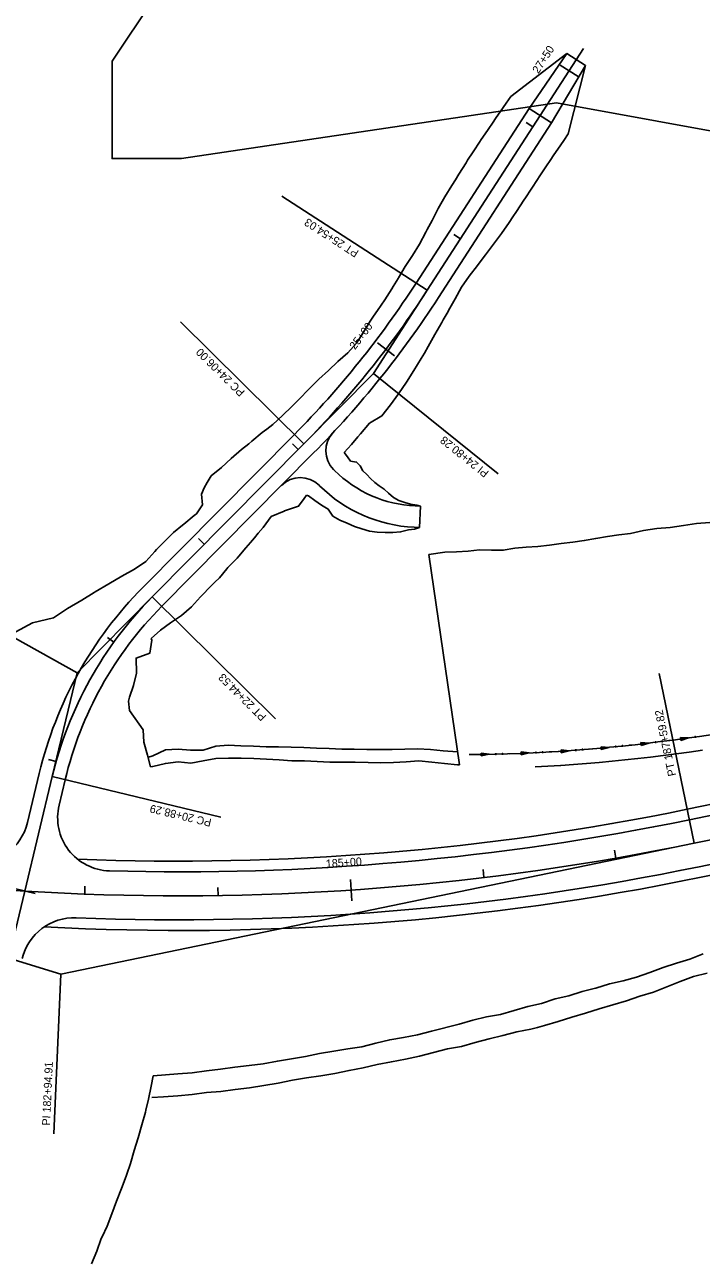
# Model space of a CAD drawing. Extents: x 979959 to 994833, y 1835619 to 1845316.
# Drawn here: x 984070 to 984578, y 1837450 to 1838378 of the extents above; entities that cross this region are included whole.
import ezdxf

# ---------------------------------------------------------------- set-up
doc = ezdxf.new("R2010")
doc.units = 0
for name, color, linetype in [('43', 7, 'Continuous'), ('Future 5 Lane Construction Limits', 7, 'Continuous'), ('R_Horz Alg', 7, 'Continuous'), ('R_Horz Alg Annot', 7, 'Continuous'), ('R_Horz Alg Annot_Side Road', 7, 'Continuous'), ('R_Horz Alg Stationing', 7, 'Continuous'), ('R_Horz Alg Stationing_Side Road', 7, 'Continuous'), ('R_Proposed Const Limits', 7, 'Continuous'), ('R_Proposed Road', 7, 'Continuous'), ('R_Special Ditch', 7, 'Continuous')]:
    doc.layers.add(name, color=color, linetype=linetype)

msp = doc.modelspace()

# ---------------------------------------------------------------- linework, layer by layer
at = {"layer": '43'}
msp.add_lwpolyline([(985729.8, 1837558.64), (985521.45, 1837673.22), (985396.47, 1837819.08), (985333.96, 1837902.41), (985188.08, 1838006.57), (985073.51, 1838162.87), (984990.18, 1838225.38), (984698.45, 1838277.45), (984469.3, 1838319.11), (984188, 1838277.43), (984135.93, 1838277.43), (984135.89, 1838350.34), (984198.39, 1838444.12), (984198.44, 1838496.23), (984083.82, 1838590), (983937.96, 1838704.54)], dxfattribs=at)
at = {"layer": 'Future 5 Lane Construction Limits'}
for points in [[(984162.55, 1837828.4), (984166.49, 1837829.56), (984175.97, 1837834.1), (984185.4, 1837834.68), (984194.82, 1837833.95), (984204.25, 1837833.77), (984213.64, 1837836.74), (984223.04, 1837837.47), (984232.46, 1837837.15), (984241.89, 1837836.8), (984251.33, 1837836.29), (984260.76, 1837836.31), (984270.21, 1837836), (984279.66, 1837835.71), (984289.13, 1837835.31), (984298.61, 1837834.96), (984308.09, 1837834.65), (984317.57, 1837834.49), (984327.05, 1837834.44), (984336.54, 1837834.43), (984346.04, 1837834.41), (984355.52, 1837834.59), (984365.02, 1837834.8), (984374.58, 1837834.36), (984384.24, 1837833.21), (984394.98, 1837832.55)], [(984165.82, 1837573.32), (984174.47, 1837573.85), (984185.26, 1837574.74), (984196.04, 1837575.66), (984206.81, 1837577.02), (984217.57, 1837577.79), (984228.31, 1837579.37), (984239.04, 1837580.66), (984249.75, 1837582.38), (984260.44, 1837584.13), (984271.11, 1837586.27), (984281.77, 1837588.14), (984292.43, 1837589.65), (984303.06, 1837591.47), (984313.66, 1837593.73), (984324.26, 1837595.65), (984334.81, 1837598.04), (984345.37, 1837600.16), (984355.93, 1837602.1), (984366.44, 1837604.43), (984376.91, 1837607.11), (984387.35, 1837609.85), (984397.87, 1837611.68), (984408.27, 1837614.54), (984418.66, 1837617.27), (984429.05, 1837619.94), (984439.42, 1837622.66), (984449.87, 1837624.59), (984454.86, 1837625.85), (984460.2, 1837627.42), (984470.49, 1837630.4), (984480.7, 1837633.75), (984490.98, 1837636.62), (984501.2, 1837639.75), (984511.38, 1837642.99), (984521.6, 1837645.95), (984531.72, 1837649.39), (984541.9, 1837652.37), (984551.86, 1837656.47), (984561.84, 1837660.37), (984571.82, 1837664.17), (984582.07, 1837666.51)]]:
    msp.add_lwpolyline(points, dxfattribs=at)
at = {"layer": 'R_Horz Alg'}
for p, q in [((984572.47, 1837764.03), (990033.82, 1838891.48)), ((984372.29, 1838178.66), (984489.55, 1838360.02)), ((984372.29, 1838178.66), (984489.55, 1838360.02)), ((984372.29, 1838178.66), (984489.55, 1838360.02)), ((984166.05, 1837948.8), (984279.68, 1838063.51)), ((984166.05, 1837948.8), (984279.68, 1838063.51)), ((984166.05, 1837948.8), (984279.68, 1838063.51)), ((984070.41, 1837728.11), (984090.99, 1837813.97)), ((984070.41, 1837728.11), (984090.99, 1837813.97)), ((984070.41, 1837728.11), (984090.99, 1837813.97)), ((984003.15, 1837447.52), (984070.41, 1837728.11))]:
    msp.add_line(p, q, dxfattribs=at)
for centre, radius, start, end in [((983770.86, 1838567.53), 716.2, 315.27137, 327.11389), ((983770.86, 1838567.53), 716.2, 315.27137, 327.11389), ((983770.86, 1838567.53), 716.2, 315.27137, 327.11389), ((984369.58, 1837747.19), 286.48, 135.27137, 166.51989), ((984369.58, 1837747.19), 286.48, 135.27137, 166.51989), ((984369.58, 1837747.19), 286.48, 135.27137, 166.51989), ((984186.34, 1839634.45), 1909.86, 253.16792, 281.66438)]:
    msp.add_arc(centre, radius, start, end, dxfattribs=at)
at = {"layer": 'R_Horz Alg Annot'}
for points in [[(984572.47, 1837764.03), (984546.19, 1837891.35)], [(984097.51, 1837665.98), (984092.1, 1837546.1)]]:
    msp.add_lwpolyline(points, dxfattribs=at)
at = {"layer": 'R_Horz Alg Annot_Side Road'}
for p, q in [((984331.96, 1838116.28), (984372.29, 1838178.66)), ((984331.96, 1838116.28), (984279.68, 1838063.51)), ((984109.67, 1837891.88), (984166.05, 1837948.8)), ((984090.99, 1837813.97), (984109.67, 1837891.88)), ((983633.31, 1837806.41), (984097.51, 1837665.98)), ((984572.47, 1837764.03), (984097.51, 1837665.98))]:
    msp.add_line(p, q, dxfattribs=at)
for points in [[(984372.29, 1838178.66), (984263.12, 1838249.25)], [(984279.68, 1838063.51), (984187.32, 1838155)], [(984331.96, 1838116.28), (984425.47, 1838041.08)], [(984109.67, 1837891.88), (984004.82, 1837950.25)], [(984166.05, 1837948.8), (984258.41, 1837857.31)], [(984090.99, 1837813.97), (984217.41, 1837783.66)]]:
    msp.add_lwpolyline(points, dxfattribs=at)
at = {"layer": 'R_Horz Alg Stationing'}
for points in [[(984512.69, 1837758.77), (984513.71, 1837752.86)], [(984314.7, 1837736.93), (984315.78, 1837720.96)], [(984414.07, 1837744.26), (984414.79, 1837738.3)], [(984115.58, 1837731.91), (984115.35, 1837725.91)], [(984215.25, 1837730.81), (984215.34, 1837724.81)]]:
    msp.add_lwpolyline(points, dxfattribs=at)
at = {"layer": 'R_Horz Alg Stationing_Side Road'}
for points in [[(984471.98, 1838347.57), (984485.41, 1838338.88)], [(984446.51, 1838304.5), (984451.55, 1838301.24)], [(984392.21, 1838220.52), (984397.25, 1838217.26)], [(984334.9, 1838139.28), (984347.64, 1838129.6)], [(984271.2, 1838063.47), (984275.46, 1838059.25)], [(984200.82, 1837992.43), (984205.08, 1837988.2)], [(984132.42, 1837918.37), (984137.29, 1837914.86)], [(984088.18, 1837826.93), (984093.95, 1837825.3)], [(984062.63, 1837729.98), (984078.19, 1837726.25)]]:
    msp.add_lwpolyline(points, dxfattribs=at)
at = {"layer": 'R_Proposed Const Limits'}
for p, q in [((984434.96, 1838323.87), (984476.93, 1838356.27)), ((984478.05, 1838296.01), (984490.99, 1838347.18)), ((984396.12, 1837628.41), (984375.41, 1837623.02))]:
    msp.add_line(p, q, dxfattribs=at)
for points in [[(984319.16, 1838139.02), (984324.33, 1838147.3), (984329.47, 1838155.56), (984332.04, 1838159.27), (984334.96, 1838163.55), (984340.37, 1838171.59), (984345.58, 1838179.76), (984346.69, 1838181.54), (984350.33, 1838187.39), (984350.69, 1838187.98), (984355.77, 1838196.45), (984361.2, 1838204.85), (984366.55, 1838213.29), (984371.19, 1838222.21), (984372.17, 1838224.16), (984375.97, 1838231.02), (984380.35, 1838240.1), (984385.45, 1838248.71), (984390.74, 1838257.2), (984393.43, 1838261.49), (984395.98, 1838265.72), (984401.32, 1838274.17), (984402.56, 1838276.12), (984406.71, 1838282.59), (984412.05, 1838290.51), (984412.31, 1838290.89), (984417.94, 1838299.15), (984421.75, 1838304.77), (984423.55, 1838307.43), (984429.15, 1838315.72), (984431.4, 1838319.06), (984434.96, 1838323.87)], [(984398.03, 1838181.04), (984403.68, 1838189.29), (984409.94, 1838197.15), (984411.25, 1838198.88), (984415.97, 1838205.16), (984421.94, 1838213.21), (984427.83, 1838221.31), (984433.6, 1838229.49), (984436.45, 1838233.67), (984439.23, 1838237.75), (984444.71, 1838246.12), (984445.99, 1838248.04), (984450.24, 1838254.45), (984455.41, 1838262.48), (984455.63, 1838262.87), (984461.14, 1838271.22), (984464.95, 1838276.84), (984466.8, 1838279.47), (984472.47, 1838287.71), (984474.72, 1838291.05), (984478.05, 1838296.01)], [(984309.89, 1838057.01), (984315.41, 1838063.13), (984320.28, 1838068.69), (984322.21, 1838070.95), (984328.85, 1838078.9), (984338.3, 1838084.46), (984344.63, 1838092.72), (984350.78, 1838101.13), (984350.79, 1838101.14), (984356.63, 1838109.74), (984362.23, 1838118.53), (984367.67, 1838127.39), (984370.11, 1838131.57), (984372.89, 1838136.39), (984378.04, 1838145.4), (984383.08, 1838154.45), (984384.17, 1838156.42), (984387.85, 1838162.77), (984388.21, 1838163.42), (984393.15, 1838172.28), (984398.03, 1838181.04)], [(984199.09, 1838011), (984203.7, 1838017.73), (984202.99, 1838025.85), (984204.98, 1838030.54), (984207.12, 1838034.56), (984210.13, 1838039.51), (984217.9, 1838045.89), (984225.15, 1838052.43), (984225.3, 1838052.63), (984232.89, 1838059.19), (984238.51, 1838063.47), (984240.7, 1838065.53), (984248.46, 1838071.92), (984251.94, 1838074.44), (984256.4, 1838078.13), (984263.65, 1838084.82), (984270.64, 1838091.46), (984277.52, 1838098.22), (984282.32, 1838103.15), (984284.23, 1838105.15), (984290.95, 1838112.09), (984298.16, 1838118.63), (984305.3, 1838125.28), (984312.71, 1838131.74), (984312.73, 1838131.75), (984319.16, 1838139.02)], [(984309.89, 1838057.01), (984312.38, 1838053.89), (984314.76, 1838050.57), (984319.2, 1838049.79), (984321.97, 1838047.12), (984323.96, 1838043.18), (984326.98, 1838040.55), (984329.81, 1838037.42), (984332.94, 1838034.58), (984336.29, 1838031.94), (984339.82, 1838029.49), (984343.3, 1838026.42), (984346.98, 1838023.35), (984351.02, 1838021.09), (984355.33, 1838019.64), (984359.73, 1838018.33), (984364.35, 1838017.46), (984367.11, 1838016.75)], [(984255.18, 1838008.96), (984264.95, 1838013.01), (984265.11, 1838013.2), (984275.75, 1838016.74), (984279.85, 1838022.52), (984281.75, 1838025.11)], [(984281.75, 1838025.11), (984283.29, 1838024.52), (984288.05, 1838021.05), (984292.9, 1838017.63), (984298, 1838014.63), (984301.5, 1838009.32), (984306.65, 1838006.3), (984312.16, 1838003.97), (984317.62, 1838001.66), (984323.19, 1837999.69), (984328.85, 1837998.02), (984334.76, 1837997.34), (984340.66, 1837997.04), (984346.53, 1837997.16), (984352.3, 1837997.43), (984358.08, 1837998.99), (984362.78, 1837999.55), (984366.35, 1838000.77)], [(984063.84, 1837922.44), (984076.19, 1837929.25), (984092, 1837933.17), (984102.5, 1837939.97), (984113.15, 1837946.26), (984122.54, 1837952.07), (984123.27, 1837952.56), (984133.43, 1837958.49), (984143.23, 1837964.42), (984152.79, 1837969.63), (984161.23, 1837975.34), (984168.04, 1837982.68), (984169.29, 1837984.36), (984174.88, 1837989.97), (984178.67, 1837993.79), (984182.06, 1837996.93), (984188.78, 1838002.5), (984189.83, 1838003.32), (984197.58, 1838009.71), (984199.09, 1838011)], [(984165.26, 1837917.55), (984172.3, 1837923.71), (984179.77, 1837929.35), (984187.91, 1837934.84), (984195.49, 1837941.41), (984202.32, 1837948.71), (984203.74, 1837950.24), (984209.1, 1837956.07), (984213.01, 1837959.77), (984216.35, 1837962.97), (984221.89, 1837969.7), (984222.73, 1837970.72), (984229.75, 1837977.85), (984231.04, 1837979.35), (984236.29, 1837985.44), (984239.74, 1837989.44), (984242.82, 1837993.05), (984245.54, 1837996.5), (984249.12, 1838000.89), (984255.18, 1838008.96)], [(984385.39, 1837982.33), (984394.14, 1837982.58), (984402.88, 1837982.96), (984411.53, 1837984.07), (984420.37, 1837983.87), (984429.21, 1837983.74), (984437.83, 1837985.2), (984446.39, 1837985.99), (984446.54, 1837986), (984455.29, 1837986.65), (984464.02, 1837987.44), (984472.68, 1837988.69), (984481.37, 1837989.8), (984490.04, 1837990.99), (984498.66, 1837992.55), (984507.3, 1837993.96), (984515.98, 1837995.2), (984524.71, 1837996.32), (984534.45, 1837998.6), (984544.38, 1837999.94), (984554.39, 1838000.9), (984564.34, 1838002.2), (984574.24, 1838003.67), (984584.29, 1838004.48)], [(984385.39, 1837982.33), (984373.52, 1837980.5), (984396.4, 1837822.75)], [(984164.71, 1837821.21), (984162.34, 1837830.17), (984159.78, 1837839.82), (984159.2, 1837848.99), (984148.95, 1837863.62), (984148.1, 1837870.48), (984149.02, 1837873.62), (984151.99, 1837882.22), (984154.1, 1837891.56), (984153.91, 1837902.86), (984164.24, 1837906.59), (984165.74, 1837916.25), (984165.26, 1837917.55)], [(984164.71, 1837821.21), (984166.41, 1837821.68), (984175.91, 1837823.92), (984185.39, 1837824.99), (984194.87, 1837824.11), (984204.33, 1837825.9), (984213.78, 1837827.59), (984223.24, 1837827.85), (984232.7, 1837827.92), (984242.18, 1837827.48), (984251.66, 1837827.06), (984261.16, 1837826.58), (984270.68, 1837825.95), (984280.18, 1837825.79), (984289.7, 1837825.33), (984299.23, 1837824.94), (984308.75, 1837824.84), (984318.28, 1837824.8), (984327.82, 1837824.59), (984337.38, 1837824.38), (984346.91, 1837824.59), (984356.42, 1837825.01), (984365.9, 1837825.89), (984375.59, 1837824.71), (984385.28, 1837823.78), (984395, 1837822.73), (984396.4, 1837822.75)], [(984396.12, 1837628.41), (984406.43, 1837631.27), (984416.75, 1837633.93), (984427.16, 1837635.64), (984437.42, 1837638.52), (984447.65, 1837641.54), (984457.95, 1837643.87), (984468.09, 1837647.28), (984478.38, 1837649.58), (984488.51, 1837652.78), (984498.53, 1837655.43), (984498.71, 1837655.49), (984508.84, 1837658.55), (984519.06, 1837660.98), (984529.25, 1837663.57), (984539.27, 1837667.02), (984549.22, 1837670.77), (984559.24, 1837674.07), (984569.27, 1837677.22), (984579.15, 1837681.07)], [(984166.82, 1837589.62), (984185.27, 1837591.08), (984195.96, 1837592), (984206.64, 1837593.3), (984217.31, 1837594.62), (984227.97, 1837596.08), (984238.62, 1837597.27), (984249.25, 1837598.68), (984259.85, 1837600.64), (984270.45, 1837602.27), (984281.01, 1837604.25), (984291.56, 1837606.29), (984302.11, 1837608.13), (984312.65, 1837609.81), (984323.19, 1837611.46), (984333.64, 1837614.14), (984344.07, 1837616.71), (984354.56, 1837618.43), (984365.03, 1837620.39), (984375.41, 1837623.02)], [(984120.47, 1837448.75), (984124.41, 1837458.08), (984127.82, 1837467.55), (984128.43, 1837468.91), (984132.19, 1837476.79), (984135.83, 1837486.2), (984139.2, 1837495.67), (984142.96, 1837505.05), (984146.5, 1837514.49), (984146.97, 1837515.88), (984149.67, 1837524.01), (984152.57, 1837533.6), (984155.44, 1837543.2), (984158.24, 1837552.81), (984160.86, 1837562.46), (984161.23, 1837563.88), (984163.29, 1837572.17), (984165.26, 1837581.98), (984166.82, 1837589.62)]]:
    msp.add_lwpolyline(points, dxfattribs=at)
at = {"layer": 'R_Proposed Road'}
for p, q in [((984567.22, 1837789.49), (990028.56, 1838916.94)), ((984568.84, 1837781.66), (990030.18, 1838909.11)), ((984576.11, 1837746.4), (990037.46, 1838873.85)), ((984577.73, 1837738.57), (990039.08, 1838866.02)), ((984448.58, 1838315.07), (984476.93, 1838356.27)), ((984476.93, 1838356.27), (984490.99, 1838347.18)), ((984465.37, 1838304.21), (984490.99, 1838347.18)), ((984363.89, 1838184.09), (984448.58, 1838315.07)), ((984448.58, 1838315.07), (984465.37, 1838304.21)), ((984380.69, 1838173.23), (984465.37, 1838304.21)), ((984158.94, 1837955.84), (984272.58, 1838070.55)), ((984173.15, 1837941.76), (984286.79, 1838056.47)), ((984302.01, 1838044.21), (984302.75, 1838043.48)), ((984291.14, 1838032.45), (984291.49, 1838032.11)), ((984363.11, 1838016.94), (984367.11, 1838016.75)), ((984367.11, 1838016.75), (984366.35, 1838000.77)), ((984366.35, 1838000.77), (984362.35, 1838000.96)), ((984081.27, 1837816.3), (984072.46, 1837779.58)), ((984100.72, 1837811.64), (984096.16, 1837792.62))]:
    msp.add_line(p, q, dxfattribs=at)
for centre, radius, start, end in [((983770.86, 1838567.53), 706.2, 315.27137, 327.11389), ((983770.86, 1838567.53), 726.2, 315.27137, 327.11389), ((984316.25, 1838058.26), 20, 136.96135, 224.62497), ((984367.49, 1838108.84), 92, 225.27137, 267.27137), ((984277.07, 1838018.24), 20, 45.27137, 135.27137), ((984367.49, 1838108.84), 108, 225.27137, 267.27137), ((984277.41, 1838017.9), 20, 45.27126, 45.27137), ((984369.58, 1837747.19), 296.48, 135.27137, 166.51989), ((984369.58, 1837747.19), 276.48, 135.27137, 166.51989), ((984135.06, 1837783.3), 40, 166.51989, 268.41302), ((984186.34, 1839634.45), 1883.86, 267.67679, 281.66438), ((984033.57, 1837788.9), 40, 265.26778, 346.51989), ((984186.34, 1839634.45), 1891.86, 268.41302, 281.66438), ((984186.34, 1839634.45), 1927.86, 267.70261, 281.66438), ((984186.34, 1839634.45), 1935.86, 266.99808, 281.66438), ((984107.46, 1837668.17), 40, 87.70261, 166.51989)]:
    msp.add_arc(centre, radius, start, end, dxfattribs=at)
at = {"layer": 'R_Special Ditch'}
for p, q in [((984538.49, 1837839.15), (984532.4, 1837839.51)), ((984532.4, 1837839.51), (984532.65, 1837837.41)), ((984532.65, 1837837.41), (984538.49, 1837839.15)), ((984568.27, 1837843.04), (984562.18, 1837843.27)), ((984562.18, 1837843.27), (984562.47, 1837841.17)), ((984562.47, 1837841.17), (984568.27, 1837843.04)), ((984418.68, 1837830.75), (984412.66, 1837831.69)), ((984412.66, 1837831.69), (984412.7, 1837829.57)), ((984412.7, 1837829.57), (984418.68, 1837830.75)), ((984448.7, 1837831.72), (984442.66, 1837832.52)), ((984442.66, 1837832.52), (984442.75, 1837830.41)), ((984442.75, 1837830.41), (984448.7, 1837831.72)), ((984478.69, 1837833.43), (984472.63, 1837834.06)), ((984472.63, 1837834.06), (984472.78, 1837831.95)), ((984472.78, 1837831.95), (984478.69, 1837833.43)), ((984508.62, 1837835.94), (984502.55, 1837836.45)), ((984502.55, 1837836.45), (984502.74, 1837834.34)), ((984502.74, 1837834.34), (984508.62, 1837835.94))]:
    msp.add_line(p, q, dxfattribs=at)
for points in [[(984403.68, 1837830.52), (984413.25, 1837830.64), (984422.83, 1837830.84), (984432.4, 1837831.1), (984441.98, 1837831.44), (984451.56, 1837831.84), (984461.14, 1837832.32), (984470.54, 1837832.86), (984470.71, 1837832.87), (984480.28, 1837833.54), (984489.84, 1837834.28), (984499.41, 1837835.09), (984508.96, 1837835.97), (984518.52, 1837836.93), (984528.06, 1837837.95), (984537.61, 1837839.05), (984547.14, 1837840.21), (984556.68, 1837841.45), (984566.61, 1837842.81), (984576.53, 1837844.19), (984586.46, 1837845.6)], [(984523.58, 1837837.47), (984528.06, 1837837.95), (984537.61, 1837839.05), (984538.48, 1837839.15)], [(984553.37, 1837841.02), (984553.41, 1837841.02)], [(984553.41, 1837841.02), (984556.68, 1837841.45), (984566.61, 1837842.81), (984568.27, 1837843.04)], [(984403.68, 1837830.52), (984413.25, 1837830.64), (984418.68, 1837830.75)], [(984433.67, 1837831.15), (984433.71, 1837831.15)], [(984433.71, 1837831.15), (984441.98, 1837831.44), (984448.7, 1837831.72)], [(984453.11, 1837821.31), (984462.74, 1837821.79), (984472.2, 1837822.34), (984472.37, 1837822.35), (984482, 1837823.03), (984491.62, 1837823.78), (984501.23, 1837824.6), (984510.84, 1837825.49), (984520.45, 1837826.46), (984530.05, 1837827.49), (984539.65, 1837828.59), (984549.24, 1837829.77), (984558.83, 1837831.02), (984568.76, 1837832.38), (984578.69, 1837833.76)], [(984463.68, 1837832.47), (984463.72, 1837832.47)], [(984463.72, 1837832.47), (984470.54, 1837832.86), (984470.71, 1837832.87), (984478.69, 1837833.43)], [(984493.64, 1837834.6), (984493.68, 1837834.61)], [(984493.68, 1837834.61), (984499.41, 1837835.09), (984508.62, 1837835.94)], [(984523.54, 1837837.47), (984523.58, 1837837.47)]]:
    msp.add_lwpolyline(points, dxfattribs=at)
for centre in [(984543.45, 1837839.8), (984548.42, 1837840.41), (984573.22, 1837843.77), (984423.68, 1837830.9), (984428.69, 1837831.03), (984453.7, 1837831.99), (984458.7, 1837832.24), (984483.68, 1837833.84), (984488.67, 1837834.23), (984513.6, 1837836.47), (984518.58, 1837836.97)]:
    msp.add_circle(centre, 0.375, dxfattribs=at)

# ---------------------------------------------------------------- texts
at = {"layer": 'R_Horz Alg Annot'}
for s, rotation, p in [('PT 187+59.82', 101.66438, (984558.9, 1837814.97)), ('PI 182+94.91', 87.41615, (984089.37, 1837552.23))]:
    msp.add_text(s, height=6, rotation=rotation, dxfattribs=at).set_placement(p)
at = {"layer": 'R_Horz Alg Annot_Side Road'}
for s, rotation, p in [('PT 25+54.03', 147.11389, (984321.43, 1838207.97)), ('PC 24+06.00', 135.27137, (984235.86, 1838102.7)), ('PI 24+80.28', 141.19263, (984418.91, 1838042.5)), ('PT 22+44.53', 135.27137, (984252.03, 1837859.4)), ('PC 20+88.29', 166.51989, (984210.88, 1837782.15))]:
    msp.add_text(s, height=6, rotation=rotation, dxfattribs=at).set_placement(p)
at = {"layer": 'R_Horz Alg Stationing'}
msp.add_text('185+00', height=6, rotation=3.86989, dxfattribs=at).set_placement((984296.42, 1837745.71))
at = {"layer": 'R_Horz Alg Stationing_Side Road'}
for s, rotation, p in [('27+50', 57.11389, (984455.63, 1838340.7)), ('25+00', 52.79152, (984318.08, 1838133.66))]:
    msp.add_text(s, height=6, rotation=rotation, dxfattribs=at).set_placement(p)

doc.saveas('drawing.dxf')
